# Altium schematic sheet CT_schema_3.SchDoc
size 282 x 169 mm
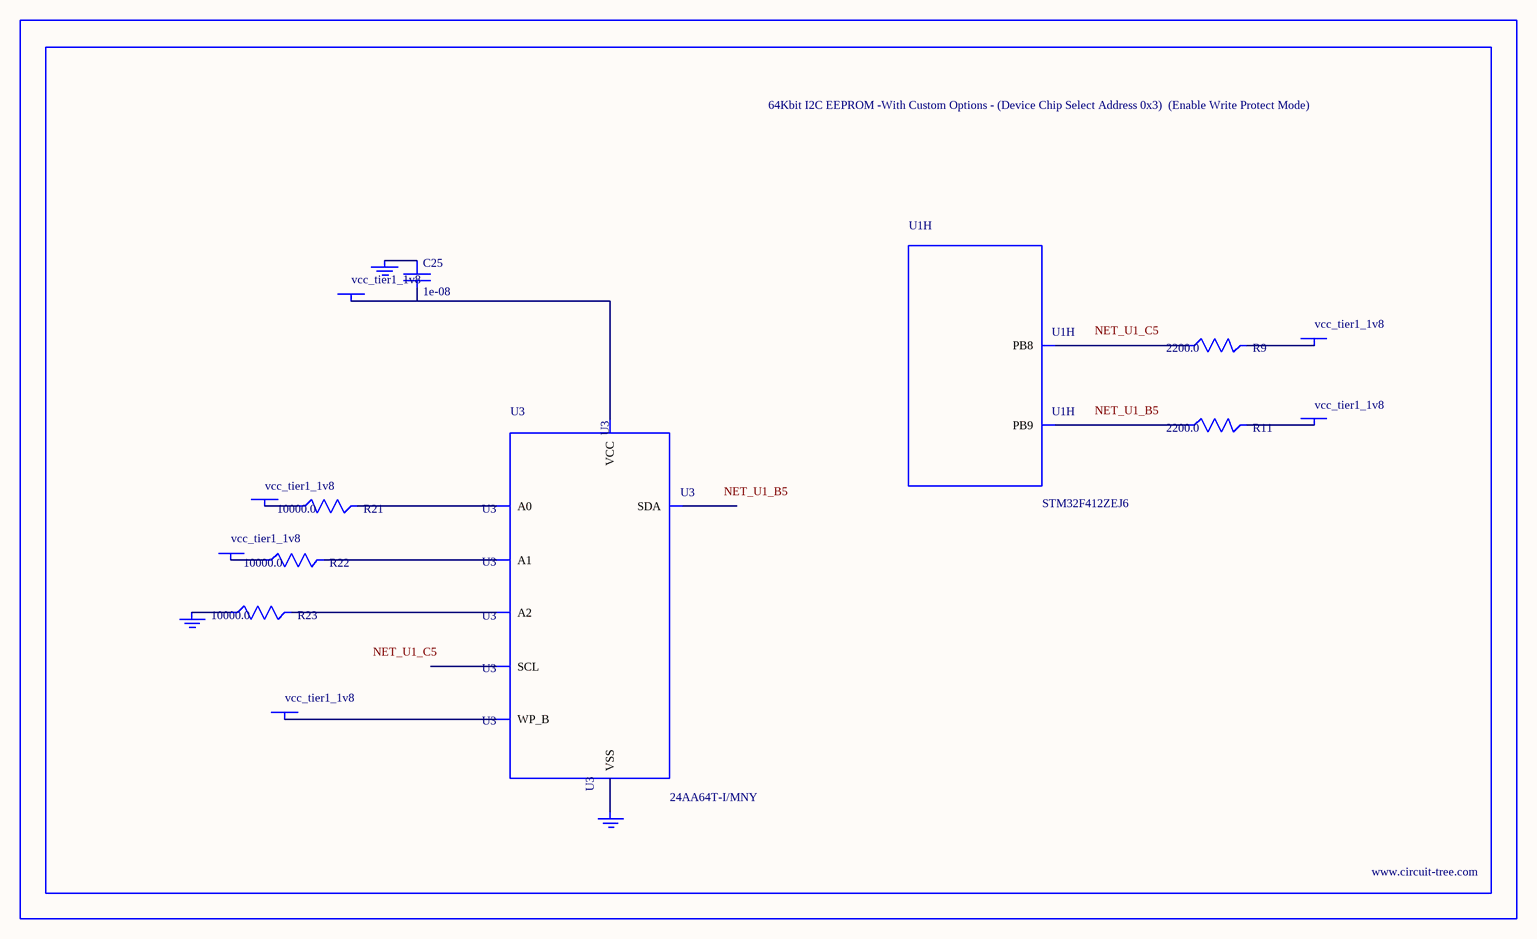
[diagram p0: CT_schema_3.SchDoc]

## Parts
BORDER2  (no value)
C25  1e-08  [C0402]
GND_INSTANCE_2_0  (no value)
GND_INSTANCE_2_1  (no value)
GND_INSTANCE_2_2  (no value)
POWER_INSTANCE_2_0  vcc_tier1_1v8
POWER_INSTANCE_2_1  vcc_tier1_1v8
POWER_INSTANCE_2_2  vcc_tier1_1v8
POWER_INSTANCE_2_3  vcc_tier1_1v8
POWER_INSTANCE_2_4  vcc_tier1_1v8
POWER_INSTANCE_2_5  vcc_tier1_1v8
R9  2200.0  [R0603]
R11  2200.0  [R0603]
R21  10000.0  [R0603]
R22  10000.0  [R0603]
R23  10000.0  [R0603]
U1  STM32F412ZEJ6  [UFBGA144]  (part H of 11)
U3  24AA64T-I/MNY  [TDFN-8/6MM]

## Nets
NetC25_1: C25.1 GND_INSTANCE_2_1.0(GND)
NetC25_2: C25.2 POWER_INSTANCE_2_3.0(PWR) U3.8(VCC)
NetGND_INSTANCE_2_0_0: GND_INSTANCE_2_0.0(GND) R23.1
NetGND_INSTANCE_2_2_0: GND_INSTANCE_2_2.0(GND) U3.4(VSS)
NetPOWER_INSTANCE_2_0_0: POWER_INSTANCE_2_0.0(PWR) R21.1
NetPOWER_INSTANCE_2_1_0: POWER_INSTANCE_2_1.0(PWR) R22.1
NetPOWER_INSTANCE_2_2_0: POWER_INSTANCE_2_2.0(PWR) U3.7(WP_B)
NetPOWER_INSTANCE_2_4_0: POWER_INSTANCE_2_4.0(PWR) R9.2
NetPOWER_INSTANCE_2_5_0: POWER_INSTANCE_2_5.0(PWR) R11.2
NetR9_1: R9.1 U1.C5(PB8)
NetR11_1: R11.1 U1.B5(PB9)
NetR21_2: R21.2 U3.1(A0)
NetR22_2: R22.2 U3.2(A1)
NetR23_2: R23.2 U3.3(A2)

Not connected (* = marked no-connect by the designer): U3 5(SDA) 6(SCL)

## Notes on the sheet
- Labels drawn without touching a wire or pin: NET_U1_B5, NET_U1_C5

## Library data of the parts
BORDER2 = BORDER_PAGE2
C25 = C0402C103K3RAC
GND_INSTANCE_2_0-GND_INSTANCE_2_2 = GND
POWER_INSTANCE_2_0-POWER_INSTANCE_2_5 = PWR
R9 R11 = RC0603JR-072K2L
R21-R23 = RC0603JR-0710KL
